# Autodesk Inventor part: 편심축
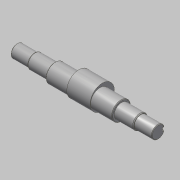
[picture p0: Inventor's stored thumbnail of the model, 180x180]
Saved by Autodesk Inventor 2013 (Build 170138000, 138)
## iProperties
Created: 2015-10
Part Number: 편심축
Document SubType Name: Modeling
Designer: mdu
Density: 7.86 g/cm^3
Material: 강철, 연강
Mass: 1327.14 g
Surface Area: 247.482 cm^2
Volume: 168.848 cm^3
Author: mdu
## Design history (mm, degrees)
sketch "스케치1"
  geometry: L1 (-20.5, -41.331)-(-20.5, 32.669) reference; L2 (7.5, -30.031)-(7.5, 21.369) reference; L3 (135.5, -30.331)-(135.5, 21.669) reference; L4 (121.5, 21.369)-(121.5, -30.031) reference; L5 (184.5, -4.331)-(-57.5, -4.331); L6 (184.5, -4.331)-(184.5, 6.669); L7 (154.5, 8.169)-(121.5, 8.169); L8 (121.5, 8.169)-(121.5, 11.669); L9 (121.5, 11.669)-(7.5, 11.669); L10 (7.5, 11.669)-(7.5, 8.169); L11 (7.5, 8.169)-(-27.5, 8.169); L12 (-27.5, 8.169)-(-27.5, 6.669); L13 (-27.5, 6.669)-(-57.5, 6.669); L14 (-57.5, 6.669)-(-57.5, -4.331); L15 (154.5, 8.169)-(154.5, 6.669); L16 (154.5, 6.669)-(184.5, 6.669); C1 r 32.5 at (64.5, -4.331) reference; 1 further point
  constraints: 24 end point, 8 perpendicular, 5 point on line, 3 parallel, 2 collinear
  dimensions: "d1" = 25 diameter of L11 L5; "d2" = 32 diameter of L9 L5; "d3" = 22 diameter of L13 L5; "d4" = 35 distance of L10.end L11.end; "d5" = 30 distance of L12.end L13.end; "d15" = 33 distance of L7.start L7.end; "d26" = 30 distance of L15.end L6.end
revolve "회전1" sketch "스케치1" stored, may be unused: angle "d6" = 90 deg
node "작업 평면1"
sketch "스케치2"
  geometry: C1 r 16 at (0, 0) reference; C2 r 16 at (0, 0) reference; C3 r 20.75 at (0, 4); C4 r 16 at (0, 0) reference; 1 further point
  constraints: 1 centre point, 1 vertical alignment
  dimensions: "d8" = 41.5 diameter of C3; "d25" = 4 distance of C3.centre C1.centre
extrude "돌출1" join sketch "스케치2" stored distance "d9" = 40; taper "d10" = 0 deg
chamfer "모따기1" distance "d11" = 1; stored, may be unused: second distance "d12" = 2, angle "d13" = 45 deg
node "작업 평면2"
sketch "스케치3"
  geometry: L1 (-15, -10)-(-15, 10) reference; L2 (-15, 3)-(0, 3); L3 (0, -3)-(-15, -3); A1 r 3 centre (0, 0) between (0, -3) and (0, 3); 2 further points
  constraints: 4 end point, 2 perpendicular, 2 point on circle, 2 point on line, 2 tangent, 1 centre point, 1 horizontal alignment, 1 midpoint
  dimensions: "d16" = 18 dimension on A1 L1; "d17" = 6 distance between parallel lines of L3 L2
extrude "돌출2" cut sketch "스케치3" distance "d18" = 3.5; taper "d19" = 0 deg
node "작업 평면3"
chamfer "모따기2" distance "d27" = 1.5; stored, may be unused: second distance "d28" = 2, angle "d29" = 30 deg
chamfer "모따기3" distance "d30" = 1.5; stored, may be unused: second distance "d31" = 2, angle "d32" = 30 deg
node "솔리드1"
mirror "대칭1"
node "참조1"
node "참조2"
node "참조3"
node "참조4"
node "참조5"
node "투영된 루프1"
